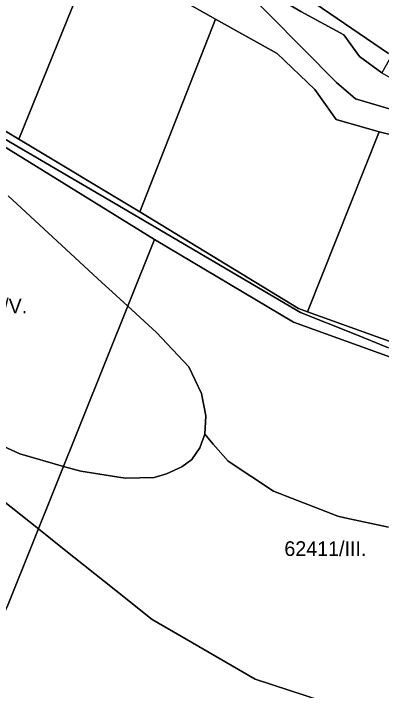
# Model space of a CAD drawing. Extents: x -522079 to -518833, y -1142400 to -1139961.
# Drawn here: x -520127.5 to -520002.4, y -1141173.1 to -1140942.7 of the extents above; entities that cross this region are included whole.
import ezdxf

# ---------------------------------------------------------------- set-up
doc = ezdxf.new("R2010")
doc.units = 0
for name, color, linetype in [('95560013', 7, 'Continuous'), ('95610013', 7, 'Continuous'), ('95630013', 7, 'Continuous'), ('95640013', 7, 'Continuous'), ('95660013', 7, 'Continuous')]:
    doc.layers.add(name, color=color, linetype=linetype)

msp = doc.modelspace()

# ---------------------------------------------------------------- linework, layer by layer
at = {"layer": '95560013'}
for points in [[(-520205.51, -1141057.7), (-520170.88, -1140963.13), (-520079.53, -1141019.58), (-520129.38, -1141144.09), (-520158.56, -1141206.98), (-520178.85, -1141202.22), (-520209, -1141207.86), (-520194.38, -1141159.65), (-520235.62, -1141148.58), (-520200.4, -1141059.73)], [(-520079.53, -1141019.58), (-520032.33, -1141047.7), (-519951.21, -1141077.01), (-519948.1, -1141084.44), (-519980.55, -1141165.39), (-520014.17, -1141252.24), (-520020.92, -1141254.2), (-520158.56, -1141206.98), (-520129.38, -1141144.09)]]:
    msp.add_lwpolyline(points, close=True, dxfattribs=at)
at = {"layer": '95610013'}
for points in [[(-520022.73, -1140882.19), (-519999.48, -1140892), (-519969.45, -1140904.62), (-520002.28, -1140962.91), (-520009.84, -1140957.29), (-520015.17, -1140949.95), (-520029.76, -1140941.98), (-520046.33, -1140932.29), (-520051.93, -1140931.48), (-520055.67, -1140929.56)], [(-520129.31, -1140925.55), (-520124.49, -1140925.8), (-520100.12, -1140914.78), (-520097.88, -1140916.76), (-520125.63, -1140985.48), (-520147.43, -1140972.36)], [(-520097.88, -1140916.76), (-520079.83, -1140932.73), (-520058.84, -1140944.58), (-520084.54, -1141010.19), (-520125.63, -1140985.48)], [(-520017.73, -1140978.78), (-520003.11, -1140982.94), (-520027.48, -1141044.21), (-520030.55, -1141043.1), (-520084.54, -1141010.19), (-520058.84, -1140944.58), (-520037.81, -1140956.24), (-520025.01, -1140968.52)], [(-520003.11, -1140982.94), (-519978.85, -1140988.86), (-519967.54, -1140984.38), (-519966.67, -1140989.91), (-519961.08, -1140991.39), (-519988.12, -1141058.45), (-520027.48, -1141044.21)]]:
    msp.add_lwpolyline(points, close=True, dxfattribs=at)
at = {"layer": '95630013'}
for points in [[(-519978.85, -1140988.86), (-520003.11, -1140982.94), (-520017.73, -1140978.78), (-520025.01, -1140968.52), (-520037.81, -1140956.24), (-520058.84, -1140944.58), (-520079.83, -1140932.73)], [(-520051.93, -1140931.48), (-520017.69, -1140966.19), (-520011.16, -1140971.75), (-519979.37, -1140981.19)]]:
    msp.add_lwpolyline(points, dxfattribs=at)
at = {"layer": '95640013'}
for points in [[(-520079.53, -1141019.58), (-520170.88, -1140963.13), (-520175.23, -1140960.44), (-520178.74, -1140956.58), (-520181.77, -1140953.24), (-520180.26, -1140950.09), (-520156.19, -1140899.86), (-520151.68, -1140896.26), (-520149.94, -1140892.73), (-520146.75, -1140896.12), (-520154.18, -1140907.23), (-520173.77, -1140949.3), (-520172.97, -1140956.99), (-520147.43, -1140972.36), (-520125.63, -1140985.48), (-520084.54, -1141010.19), (-520030.55, -1141043.1), (-520027.48, -1141044.21), (-519988.12, -1141058.45), (-519949.16, -1141072.54), (-519944.08, -1141074.41), (-519948.1, -1141084.44), (-519951.21, -1141077.01), (-520032.33, -1141047.7)], [(-520002.28, -1140962.91), (-519999.3, -1140964.63), (-519986.94, -1140971.3), (-519974.08, -1140974.02), (-519965.47, -1140973.69), (-519979.37, -1140981.19), (-520011.16, -1140971.75), (-520017.69, -1140966.19), (-520051.93, -1140931.48), (-520046.33, -1140932.29), (-520029.76, -1140941.98), (-520015.17, -1140949.95), (-520009.84, -1140957.29)]]:
    msp.add_lwpolyline(points, close=True, dxfattribs=at)
at = {"layer": '95660013'}
for points in [[(-520000, -1140956.26), (-520027.38, -1140937.41), (-520050.3, -1140921.84), (-520086.66, -1140897.15), (-520123.75, -1140875.26), (-520138.61, -1140866.5), (-520139.14, -1140866.18), (-520147.26, -1140862.91), (-520160.33, -1140857.64), (-520186.01, -1140847.28), (-520201.07, -1140841.21), (-520202.12, -1140840.78), (-520218.2, -1140835.96), (-520257.78, -1140824.09), (-520262.02, -1140822.82), (-520292.94, -1140818.09), (-520298.45, -1140817.25), (-520310.14, -1140810.09), (-520319.61, -1140804.3), (-520323.76, -1140801.76), (-520331.96, -1140791.24)], [(-520331.96, -1140791.24), (-520323.76, -1140801.76), (-520319.61, -1140804.3), (-520310.14, -1140810.09), (-520298.45, -1140817.25), (-520292.94, -1140818.09), (-520262.02, -1140822.82), (-520257.78, -1140824.09), (-520218.2, -1140835.96), (-520202.12, -1140840.78), (-520201.07, -1140841.21), (-520186.01, -1140847.28), (-520160.33, -1140857.64), (-520147.26, -1140862.91), (-520139.14, -1140866.18), (-520138.61, -1140866.5), (-520123.75, -1140875.26), (-520086.66, -1140897.15), (-520050.3, -1140921.84), (-520027.38, -1140937.41), (-520000, -1140956.26)], [(-520000, -1141056.45), (-520011.71, -1141051.75), (-520029.88, -1141044.45), (-520090.04, -1141009.08), (-520177.16, -1140958.1), (-520177.51, -1140957.94), (-520179, -1140957.22), (-520187.97, -1140952.91), (-520193.37, -1140950.32), (-520197.48, -1140948.35), (-520236.79, -1140929.49), (-520241.05, -1140927.38), (-520260.08, -1140917.96), (-520260.95, -1140917.52), (-520263.93, -1140916.05), (-520267.12, -1140914.47), (-520274.28, -1140910.93), (-520277.76, -1140909.2), (-520287.26, -1140905.6), (-520291.47, -1140904.01), (-520313.41, -1140895.68), (-520320.28, -1140893.08), (-520338.07, -1140887.2), (-520355.25, -1140881.53)], [(-520355.25, -1140881.53), (-520338.07, -1140887.2), (-520320.28, -1140893.08), (-520313.41, -1140895.68), (-520291.47, -1140904.01), (-520287.26, -1140905.6), (-520277.76, -1140909.2), (-520274.28, -1140910.93), (-520267.12, -1140914.47), (-520263.93, -1140916.05), (-520260.95, -1140917.52), (-520260.08, -1140917.96), (-520241.05, -1140927.38), (-520236.79, -1140929.49), (-520197.48, -1140948.35), (-520193.37, -1140950.32), (-520187.97, -1140952.91), (-520179, -1140957.22), (-520177.51, -1140957.94), (-520177.16, -1140958.1), (-520090.04, -1141009.08), (-520029.88, -1141044.45), (-520011.71, -1141051.75), (-520000, -1141056.45)], [(-520129.32, -1141004.76), (-520097.47, -1141034.19), (-520093.91, -1141037.44), (-520088.61, -1141042.27), (-520078.82, -1141051.21), (-520067.92, -1141062.99), (-520063.52, -1141072.02), (-520062.05, -1141079.59), (-520062.47, -1141085.9), (-520064.15, -1141090.52), (-520066.87, -1141094.52), (-520070.23, -1141097.04), (-520075.46, -1141099.35), (-520079.66, -1141100.61), (-520089.5, -1141100.82), (-520104.59, -1141098.51), (-520110.46, -1141096.84), (-520125.34, -1141092.62), (-520152.37, -1141080.22)], [(-520000, -1141117.5), (-520014.8, -1141114.31), (-520017.19, -1141113.8), (-520039.12, -1141105.26), (-520054.5, -1141095.09), (-520059.59, -1141089.22), (-520062.47, -1141085.9), (-520062.05, -1141079.59), (-520063.52, -1141072.02), (-520067.92, -1141062.99), (-520078.82, -1141051.21), (-520088.61, -1141042.27), (-520093.91, -1141037.44), (-520097.47, -1141034.19), (-520129.32, -1141004.76)], [(-520152.37, -1141080.22), (-520125.34, -1141092.62), (-520110.46, -1141096.84), (-520104.59, -1141098.51), (-520089.5, -1141100.82), (-520079.66, -1141100.61), (-520075.46, -1141099.35), (-520070.23, -1141097.04), (-520066.87, -1141094.52), (-520064.15, -1141090.52), (-520062.47, -1141085.9), (-520059.59, -1141089.22), (-520054.5, -1141095.09), (-520039.12, -1141105.26), (-520017.19, -1141113.8), (-520014.8, -1141114.31), (-520000, -1141117.5)], [(-520022.1, -1141176.82), (-520045.33, -1141169.27), (-520068.83, -1141155.61), (-520080.35, -1141148.92), (-520092.7, -1141139.06), (-520110.78, -1141124.63), (-520118.98, -1141118.13), (-520149.72, -1141093.77)], [(-520149.72, -1141093.77), (-520118.98, -1141118.13), (-520110.78, -1141124.63), (-520092.7, -1141139.06), (-520080.35, -1141148.92), (-520068.83, -1141155.61), (-520045.33, -1141169.27), (-520022.1, -1141176.82)]]:
    msp.add_lwpolyline(points, dxfattribs=at)

# ---------------------------------------------------------------- texts
for s, p in [('62454/V.', (-520149.59, -1141044.7)), ('62411/III.', (-520035.39, -1141127.33))]:
    msp.add_text(s, height=5, rotation=0, dxfattribs=at).set_placement(p)

doc.saveas('drawing.dxf')
